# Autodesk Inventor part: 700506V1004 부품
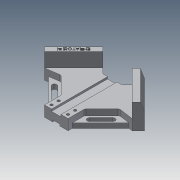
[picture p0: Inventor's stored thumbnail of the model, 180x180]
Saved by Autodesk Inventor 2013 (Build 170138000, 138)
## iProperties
Created: 2020-05
Part Number: 700506V1004 부품
Material: 알루미늄 6061
Document SubType Name: Modeling
Designer: user
Density: 2.71 g/cm^3
Mass: 573.739 g
Surface Area: 407.173 cm^2
Volume: 211.712 cm^3
Author: user
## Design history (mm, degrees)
sketch "스케치1"
  geometry: L1 (35.355, -49.497)-(84.853, 0); L2 (84.853, 0)-(20, 64.853); L3 (35.355, -49.497)-(16.005, -30.147); L4 (16.005, -30.147)-(-16.005, -30.147); L5 (-16.005, -30.147)-(-35.355, -49.497); L6 (-35.355, -49.497)-(-84.853, 0); L7 (-84.853, 0)-(-20, 64.853); L8 (20, 64.853)-(-20, 64.853); 3 further points
  constraints: 16 end point, 4 parallel, 2 midpoint, 2 perpendicular, 2 vertical alignment, 1 horizontal
  dimensions: "d0" = 120 distance between parallel lines of L7 L1; "d2" = 120 distance between parallel lines of L6 L2; "d3" = 50 distance between parallel lines of L6 L3; "d4" = 40 distance of L2.end L7.end; "d5" = 95 distance between parallel lines of L8 L4; "d7" = 50 distance between parallel lines of L5 L1; "d9" = 0 vertical distance of L1.end point (0, 0)
extrude "돌출1" new body sketch "스케치1" distance "d10" = 18; taper "d11" = 0 deg
sketch "스케치2"
  geometry: L1 (-35.355, 49.497)-(-84.853, 0) reference; L2 (-84.853, 0)-(-20, -64.853) reference; L3 (84.853, 0)-(35.355, 49.497) reference; L4 (-35.355, 49.497)-(-84.853, 0); L5 (-84.853, 0)-(-74.246, -10.607); L6 (-74.246, -10.607)-(-24.749, 38.891); L7 (-24.749, 38.891)-(-35.355, 49.497); L8 (35.355, 49.497)-(84.853, 0); L9 (84.853, 0)-(74.246, -10.607); L10 (74.246, -10.607)-(24.749, 38.891); L11 (24.749, 38.891)-(35.355, 49.497); 1 further point
  constraints: 16 end point, 5 equal length, 3 perpendicular
  dimensions: "d12" = 15 distance of L5.end L1.end; "d13" = 15 distance of L3.start L9.end
extrude "돌출2" join sketch "스케치2" distance "d14" = 24; taper "d15" = 0 deg
sketch "스케치3"
  geometry: L1 (-74.246, -10.607)-(-20, -64.853) reference; L2 (-74.246, -10.607)-(-49.497, -7.071); L3 (-49.497, -7.071)-(-20, -36.569); L4 (-20, -36.569)-(-20, -64.853); L5 (-35.355, 49.497)-(-84.853, 0) reference; L6 (-35.355, 49.497)-(-84.853, 0) reference; L7 (-84.853, 0)-(-74.246, -10.607) reference; L8 (-74.246, -10.607)-(-24.749, 38.891) reference; L9 (-24.749, 38.891)-(-35.355, 49.497) reference; L10 (-74.246, -10.607)-(-20, -64.853); 1 further point
  constraints: 8 end point, 1 collinear, 1 parallel, 1 vertical
  dimensions: "d16" = 20 distance between parallel lines of L1 L3; "d17" = 30 distance from line of L2.end L5
extrude "돌출3" cut sketch "스케치3" distance "d18" = 10; taper "d19" = 0 deg
sketch "스케치4"
  geometry: L1 (-20, -64.853)-(-74.246, -10.607) reference; L2 (-20, -36.569)-(-20, -64.853) reference; L3 (-49.497, -7.071)-(-20, -36.569) reference; L4 (-74.246, -10.607)-(-49.497, -7.071) reference; L5 (-74.246, -10.607)-(-68.059, -9.723); L6 (-68.059, -9.723)-(-20, -57.782); L7 (-20, -64.853)-(-20, -57.782); L8 (-20, -57.782)-(-20, -64.853); L9 (-74.246, -10.607)-(-20, -64.853); 1 further point
  constraints: 10 end point, 3 collinear, 2 point on line, 1 parallel
  dimensions: "d20" = 5 distance between parallel lines of L6 L1
extrude "돌출4" cut sketch "스케치4" stored distance "d21" = 10; taper "d22" = 0 deg
sketch "스케치5"
  geometry: L1 (-35.355, 49.497)-(-84.853, 0) reference; L2 (-84.853, 0)-(-74.246, -10.607) reference; L3 (-74.246, -10.607)-(-24.749, 38.891) reference; L4 (-24.749, 38.891)-(-35.355, 49.497) reference; L5 (-52.326, -21.213)-(-32.527, -41.012); L6 (-26.87, -35.355)-(-46.669, -15.556); A1 r 4 centre (-49.497, -18.385) between (-52.326, -21.213) and (-46.669, -15.556); A2 r 4 centre (-29.698, -38.184) between (-32.527, -41.012) and (-26.87, -35.355); 1 further point
  constraints: 4 end point, 4 point on circle, 2 centre point, 2 parallel
  dimensions: "d23" = 8 diameter of A1; "d24" = 8 diameter of A2; "d25" = 12 distance from line of L2 A1.centre; "d26" = 12 distance from line of L2 A2.centre; "d27" = 28 distance of A2.centre A1.centre; "d28" = 38 distance from line of A1.centre L1; "d29" = 8 distance between parallel lines of L6 L5; "d30" = 16 distance between parallel lines of L2 L6
extrude "돌출5" cut sketch "스케치5" stored distance "d31" = 10; taper "d32" = 0 deg
chamfer "모따기1" distance "d33" = 5; stored, may be unused: second distance "d34" = 15, angle "d35" = 45 deg
chamfer "모따기2" distance "d36" = 5; stored, may be unused: second distance "d37" = 15, angle "d38" = 45 deg
sketch "스케치7"
  geometry: L1 (-20, -64.853)-(20, -64.853) reference; L2 (16.005, 30.147)-(-16.005, 30.147) reference; L3 (-8, 30.147)-(8, 30.147); L4 (8, 30.147)-(8, -64.853); L5 (8, -64.853)-(-8, -64.853); L6 (-8, -64.853)-(-8, 30.147); 2 further points
  constraints: 8 end point, 2 midpoint, 2 parallel, 1 horizontal, 1 perpendicular, 1 point on line
  dimensions: "d39" = 16 distance between parallel lines of L6 L4
extrude "돌출6" cut sketch "스케치7" distance "d41" = 3.5; taper "d42" = 0 deg
sketch "스케치8"
  geometry: L1 (16.005, -30.147)-(-16.005, -30.147) reference; L2 (-20, 64.853)-(20, 64.853) reference; L3 (-6, 64.853)-(6, 64.853); L4 (6, 64.853)-(6, -30.147); L5 (6, -30.147)-(-6, -30.147); L6 (-6, -30.147)-(-6, 64.853); 2 further points
  constraints: 8 end point, 2 parallel, 2 point on line, 1 horizontal, 1 midpoint, 1 perpendicular, 1 vertical alignment
  dimensions: "d43" = 12 distance between parallel lines of L4 L6
extrude "돌출7" cut sketch "스케치8" distance "d45" = 3; taper "d46" = 0 deg
sketch "스케치10"
  geometry: L1 (-20, 64.853)-(-6, 64.853) reference; L2 (6, 64.853)-(6, -30.147) reference; L3 (16.005, -30.147)-(6, -30.147) reference; L4 (35.355, -49.497)-(16.005, -30.147) reference; L5 (84.853, 0)-(35.355, -49.497) reference; L6 (20, 64.853)-(84.853, 0) reference; L7 (6, 64.853)-(20, 64.853) reference; L8 (6, 64.853)-(6, -30.147) reference; L9 (-6, 64.853)-(6, 64.853) reference; L10 (-6, -30.147)-(-6, 64.853) reference; L11 (6, -30.147)-(-6, -30.147) reference; 5 further points
  constraints: 2 horizontal alignment, 2 vertical alignment
  dimensions: "d47" = 6 distance from line of L1 point (-14, 58.853); "d48" = 12 distance of point (-14, 58.853) point (-14, 46.853); "d49" = 14 horizontal distance of point (-14, 58.853) point (0, 0); "d50" = 14 horizontal distance of point (14, 58.853) point (0, 0)
hole "구멍1" sketch "스케치10" at (-14, 58.853), (-14, 46.853), (14, 58.853), (14, 46.853) diameter "d51" = 4.5; stored, may be unused: countersink angle "d55" = 90 deg, drill point angle "d57" = 118 deg; dims "d52" = 6, "d53" = 8, "d54" = 10, "d56" = 8
fillet "모깎기1" dims "d58" = 5
fillet "모깎기2" dims "d59" = 5
sketch "스케치11"
  geometry: L1 (-74.246, -10.607)-(-24.749, 38.891) reference; L2 (-24.749, 38.891)-(-31.82, 45.962) reference; 2 further points
  constraints: 1 other
  dimensions: "d60" = 35 distance from line of L2 point (-53.033, 17.678); "d61" = 5 distance from line of L1 point (-53.033, 17.678)
feature "엠보싱1" sketch "스케치11" dims "d0" = 120, "d2" = 120, "d3" = 50, "d4" = 40, "d5" = 95, "d7" = 50, "d9" = 0, "d13" = 15, "d62" = 0.5, "d63" = 0
node "솔리드1"
mirror "대칭1"
node "투영된 루프1"
node "투영된 루프2"
node "투영된 루프3"
node "투영된 루프4"
